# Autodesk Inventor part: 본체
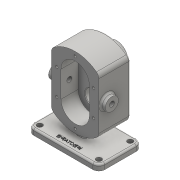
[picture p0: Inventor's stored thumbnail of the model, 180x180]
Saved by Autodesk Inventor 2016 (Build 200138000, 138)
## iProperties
Created: 2019-03
Part Number: 본체
Material: Generic
Document SubType Name: Modeling
Designer: 2-PC11
Density: 1 g/cm^3
Appearance: Default
Author: 2-PC11
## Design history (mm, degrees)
sketch "스케치1"
  geometry: L1 (-60, -36.5)-(60, -36.5); L2 (60, -36.5)-(60, 36.5); L3 (60, 36.5)-(-60, 36.5); L4 (-60, 36.5)-(-60, -36.5); L5 (-60, -36.5)-(60, 36.5); L6 (60, -36.5)-(-60, 36.5); 1 further point
  constraints: 12 end point, 2 midpoint, 2 parallel, 1 horizontal, 1 perpendicular
  dimensions: "d0" = 73 distance of L1.end L2.end; "d1" = 120 distance of L2.end L3.end
extrude "돌출1" new body sketch "스케치1" distance "d2" = 10; taper "d3" = 0 deg
sketch "스케치2"
  geometry: L1 (60, 36.5)-(-60, 36.5) reference; L2 (-6, 36.5)-(6, 36.5); L3 (6, 36.5)-(6, -6.5); L4 (6, -6.5)-(-6, -6.5); L5 (-6, -6.5)-(-6, 36.5); 2 further points
  constraints: 8 end point, 2 parallel, 1 horizontal, 1 midpoint, 1 perpendicular, 1 point on line, 1 vertical alignment
  dimensions: "d4" = 12 distance between parallel lines of L3 L5; "d5" = 43 distance of L4.end L2.start
extrude "돌출2" join sketch "스케치2" distance "d6" = 68; taper "d7" = 0 deg
sketch "스케치3"
  geometry: L1 (100, -122.721)-(100, -33.279); L2 (20, -122.721)-(20, -33.279); L3 (120, 0)-(0, 0) reference; L4 (100, -78)-(20, -78); A1 r 60 centre (60, -78) between (100, -33.279) and (20, -33.279); A2 r 60 centre (60, -78) between (20, -122.721) and (100, -122.721); 4 further points
  constraints: 6 end point, 5 midpoint, 4 point on circle, 4 vertical alignment, 2 centre point, 2 vertical
  dimensions: "d8" = 60 radius of A2; "d9" = 60 radius of A1; "d10" = 80 distance between parallel lines of L2 L1; "d11" = 40 distance from line of point (60, 0) L1; "d12" = 138 dimension on A2 L3; "d14" = 78 distance from line of point (60, 0) L4
extrude "돌출3" join sketch "스케치3" distance "d15" = 53; taper "d16" = 0 deg
sketch "스케치4"
  geometry: L1 (100, 33.279)-(100, 122.721) reference; L2 (20, 122.721)-(20, 33.279) reference; L3 (60, 100)-(60, 56); L4 (36, 100)-(36, 56); L5 (84, 56)-(84, 100); A1 r 60 centre (60, 78) between (100, 122.721) and (20, 122.721) reference; A2 r 60 centre (60, 78) between (20, 33.279) and (100, 33.279) reference; A3 r 24 centre (60, 100) between (84, 100) and (36, 100); A4 r 24 centre (60, 56) between (36, 56) and (84, 56); 2 further points
  constraints: 8 end point, 4 point on circle, 4 tangent, 2 centre point, 1 coincident, 1 midpoint, 1 parallel, 1 vertical
  dimensions: "d17" = 24 radius of A3; "d18" = 22 distance of A1.centre L3.start
extrude "돌출4" cut sketch "스케치4" distance "d19" = 29; taper "d20" = 0 deg
sketch "스케치5"
  geometry: L1 (36, 56)-(36, 100) reference; L2 (84, 100)-(84, 56) reference; C1 r 12.5 at (60, 100); C2 r 12.5 at (60, 56); A1 r 24 centre (60, 56) between (36, 56) and (84, 56) reference; A2 r 24 centre (60, 100) between (84, 100) and (36, 100) reference; 1 further point
  constraints: 2 centre point, 2 coincident, 1 equal radius
  dimensions: "d21" = 25 diameter of C1
extrude "돌출5" cut sketch "스케치5" distance "d22" = 15; taper "d23" = 0 deg
sketch "스케치6"
  geometry: C1 r 8.5 at (0, 0); C2 r 12.5 at (0, 0) reference; 1 further point
  constraints: 1 centre point, 1 concentric
  dimensions: "d24" = 17 diameter of C1
extrude "돌출6" cut sketch "스케치6" stored distance "d25" = 15; taper "d26" = 0 deg
sketch "스케치7"
  geometry: C1 r 19 at (60, -100); C2 r 8.5 at (60, -100) reference; 1 further point
  constraints: 1 centre point, 1 concentric
  dimensions: "d27" = 38 diameter of C1
extrude "돌출7" join sketch "스케치7" distance "d28" = 17; taper "d29" = 0 deg
sketch "스케치8"
  geometry: C1 r 14 at (0, 0); C2 r 19 at (0, 0) reference; 1 further point
  constraints: 1 centre point, 1 concentric
  dimensions: "d30" = 28 diameter of C1
extrude "돌출8" cut sketch "스케치8" distance "d31" = 7.3; taper "d32" = 0 deg
fillet "모깎기1" dims "d33" = 0.5
chamfer "모따기2" distance "d37" = 0.7; stored, may be unused: second distance "d38" = 2, angle "d39" = 60 deg
chamfer "모따기3" distance "d40" = 1; stored, may be unused: second distance "d41" = 2, angle "d42" = 45 deg
fillet "모깎기2" dims "d43" = 10
sketch "스케치9"
  geometry: L1 (118, -73)-(118, 0) reference; L2 (80, -53)-(0, -53) reference; C1 r 11 at (40, -39); 1 further point
  constraints: 1 centre point
  dimensions: "d44" = 78 distance from line of L1 C1.centre; "d45" = 14 distance from line of C1.centre L2; "d46" = 22 diameter of C1
extrude "돌출9" join sketch "스케치9" distance "d47" = 8; taper "d48" = 0 deg
fillet "모깎기3" dims "d49" = 3
hole "구멍1" diameter "d52" = 8.376; stored, may be unused: countersink angle "d56" = 90 deg, drill point angle "d58" = 118 deg; dims "d50" = 10, "d51" = 10, "d53" = 50, "d54" = 4, "d55" = 2, "d57" = 27.3
hole "구멍2" diameter "d61" = 8.376; stored, may be unused: countersink angle "d65" = 90 deg, drill point angle "d67" = 118 deg; dims "d59" = 10, "d60" = 10, "d62" = 50, "d63" = 4, "d64" = 2, "d66" = 27.3
fillet "모깎기4" dims "d68" = 3
fillet "모깎기5" dims "d69" = 3
fillet "모깎기6" dims "d70" = 10
fillet "모깎기7" dims "d71" = 3
fillet "모깎기8" dims "d72" = 3
sketch "스케치10"
  geometry: L1 (60, 100)-(60, 56); L2 (29, 100)-(29, 56); L3 (91, 56)-(91, 100); L4 (10, 0)-(110, 0) reference; A1 r 31 centre (60, 100) between (91, 100) and (29, 100); A2 r 31 centre (60, 56) between (29, 56) and (91, 56); 10 further points
  constraints: 8 end point, 6 point on circle, 5 coincident, 4 tangent, 2 centre point, 2 midpoint, 1 parallel, 1 vertical, 1 vertical alignment
  dimensions: "d73" = 31 radius of A1; "d74" = 22 distance of point (60, 78) L1.start; "d75" = 78 distance from line of L4 point (60, 78)
hole "구멍3" sketch "스케치10" at (60, 131), (29, 100), (29, 56), (60, 25), (91, 56), (91, 100) diameter "d76" = 4.134; stored, may be unused: countersink angle "d80" = 90 deg, drill point angle "d82" = 118 deg; dims "d77" = 10, "d78" = 4, "d79" = 2, "d81" = 12
hole "구멍4" diameter "d85" = 9; stored, may be unused: countersink angle "d89" = 90 deg, drill point angle "d91" = 0 deg; dims "d83" = 10, "d84" = 10, "d86" = 10, "d87" = 4, "d88" = 2, "d90" = 12
hole "구멍5" diameter "d94" = 9; stored, may be unused: countersink angle "d98" = 90 deg, drill point angle "d100" = 0 deg; dims "d92" = 10, "d93" = 10, "d95" = 10, "d96" = 4, "d97" = 2, "d99" = 12
hole "구멍6" diameter "d103" = 9; stored, may be unused: countersink angle "d107" = 90 deg, drill point angle "d109" = 0 deg; dims "d101" = 10, "d102" = 10, "d104" = 10, "d105" = 4, "d106" = 2, "d108" = 12
hole "구멍7" diameter "d112" = 9; stored, may be unused: countersink angle "d116" = 90 deg, drill point angle "d118" = 0 deg; dims "d110" = 10, "d111" = 10, "d113" = 10, "d114" = 4, "d115" = 2, "d117" = 12
sketch "스케치11"
  geometry: L1 (-23.597, -23.498)-(23.597, -23.498); L2 (23.597, -23.498)-(23.597, -29.502); L3 (23.597, -29.502)-(-23.597, -29.502); L4 (-23.597, -29.502)-(-23.597, -23.498); L5 (-23.597, -26.5)-(23.597, -26.5); L6 (0, -23.498)-(0, -29.502); L7 (-50, -36.5)-(50, -36.5) reference; L8 (-60, 26.5)-(-60, -26.5) reference; 1 further point
  constraints: 4 end point, 4 midpoint, 2 other
  dimensions: "d119" = 10 distance between parallel lines of L7 L5; "d120" = 60 distance between parallel lines of L6 L8
feature "엠보싱1" sketch "스케치11" dims "d0" = 73, "d1" = 120, "d8" = 60, "d9" = 60, "d10" = 80, "d11" = 40, "d12" = 138, "d14" = 78, "d121" = 0.5, "d122" = 0
node "솔리드1"
mirror "대칭1"
node "투영된 루프1"
node "투영된 루프2"
